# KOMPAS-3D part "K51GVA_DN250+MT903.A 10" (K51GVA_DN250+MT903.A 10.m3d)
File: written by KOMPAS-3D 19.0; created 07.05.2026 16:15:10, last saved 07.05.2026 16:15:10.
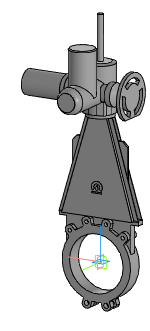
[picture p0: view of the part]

Document properties: Автор: Энергия; Полное имя файла: ..\K51GVA_DN50-DN1000+MT903.A\K51GVA_DN250+MT903.A 10.a3d

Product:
- Part/product: K51GVA_DN250+MT903.A 10
    Масса: 115.282

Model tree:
1. Операция без истории:1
